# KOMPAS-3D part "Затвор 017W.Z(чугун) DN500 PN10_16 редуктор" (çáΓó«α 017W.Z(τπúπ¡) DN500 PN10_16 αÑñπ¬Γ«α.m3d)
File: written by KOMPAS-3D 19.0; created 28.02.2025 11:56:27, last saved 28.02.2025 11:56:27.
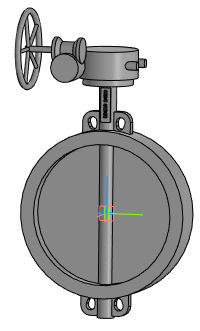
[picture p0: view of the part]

Document properties: Автор: Евгений; Полное имя файла: Затвор 017W.Z(чугун) DN500 PN10_16 редуктор.a3d

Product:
- Part/product: Затвор 017W.Z(чугун) DN500 PN10_16 редуктор
    Масса: 171.852

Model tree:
1. Операция без истории:1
